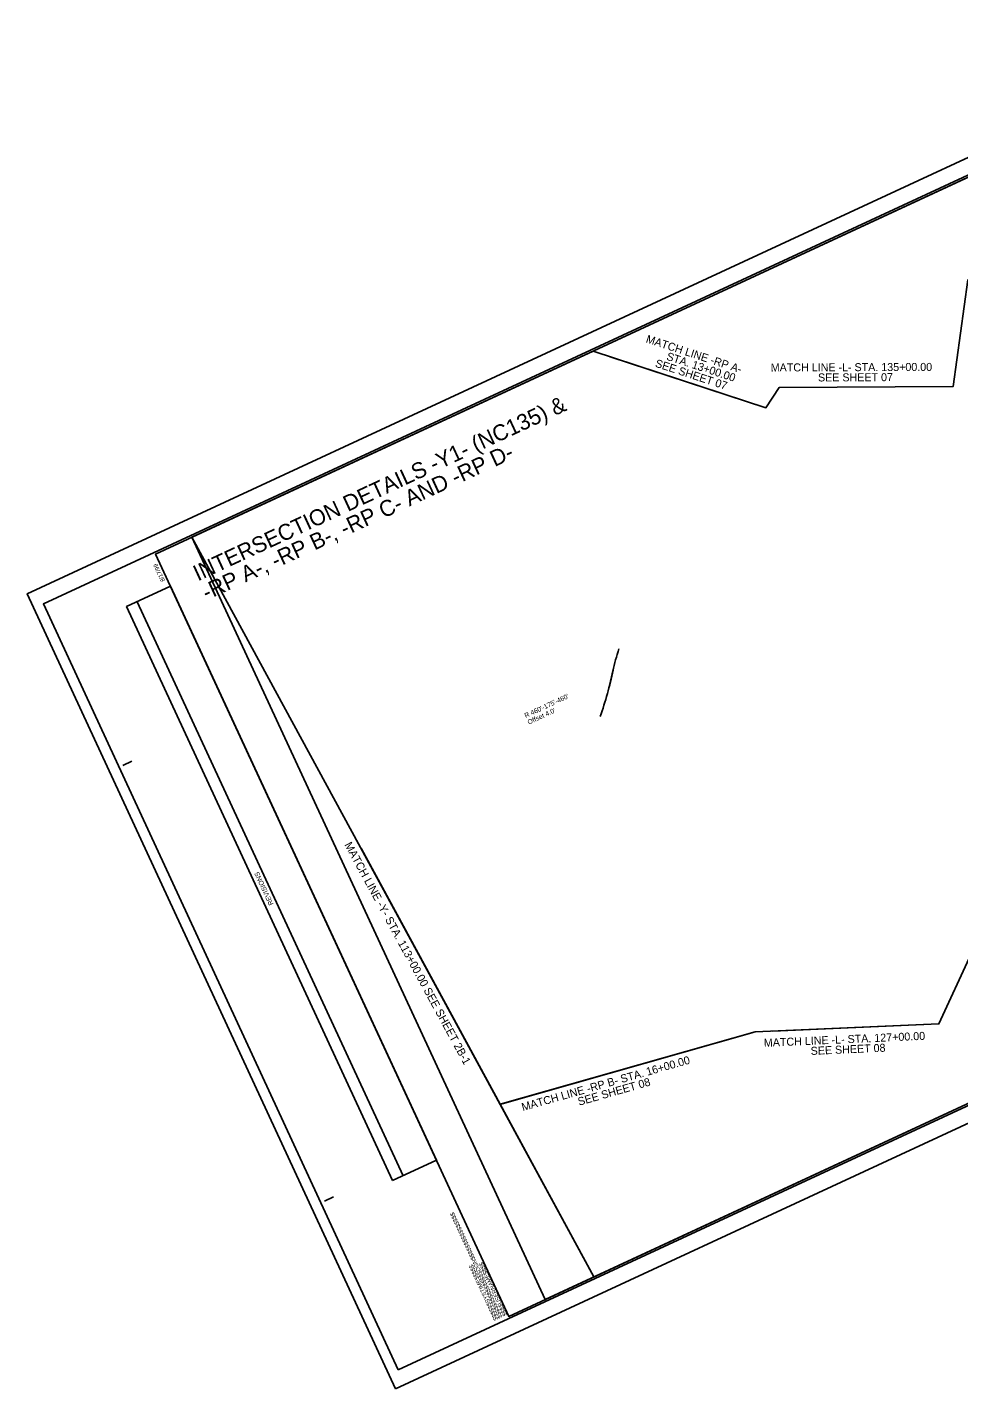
# Model space of a CAD drawing. Extents: x 1722892 to 1724880, y 971019 to 972720.
# Drawn here: x 1722892 to 1724057, y 971019 to 972720 of the extents above; entities that cross this region are included whole.
import ezdxf

# ---------------------------------------------------------------- set-up
doc = ezdxf.new("R2010")
doc.units = 0
for name, color, linetype in [('Matchline', 7, 'Continuous'), ('Matchline Text', 7, 'Continuous'), ('Prop Dimension', 7, 'Continuous'), ('Prop EOT', 7, 'Continuous'), ('Sheet Block Revision CELL', 7, 'Continuous'), ('Sheet Clip Boundary CELL', 7, 'Continuous'), ('Sheet Layout Plan Border', 7, 'Continuous'), ('Sheet Plan CELL', 7, 'Continuous'), ('Sheet Plot Border Inside CELL', 7, 'Continuous'), ('Sheet Plot Border Outside CELL', 7, 'Continuous')]:
    doc.layers.add(name, color=color, linetype=linetype)

msp = doc.modelspace()

# ---------------------------------------------------------------- linework, layer by layer
at = {"layer": 'Matchline'}
for p, q in [((1723620.9, 972308.5), (1723815.7, 972244.7)), ((1723832.3, 972270.2), (1724049.7, 972271.1)), ((1723310, 971693.4), (1723483.3, 971374.5)), ((1723797.9, 971463.5), (1723485.8, 971374.8)), ((1723824.5, 971465.6), (1724031.9, 971474.7))]:
    msp.add_line(p, q, dxfattribs=at)
at = {"layer": 'Prop Dimension'}
msp.add_line((1723620.3, 971897.8), (1723624.9, 971917.6), dxfattribs=at)
at = {"layer": 'Prop EOT'}
for centre, radius, start, end in [((1723880.9, 971861.9), 262, 161.8681, 168.1523), ((1723174.6, 972011.8), 460, 340.5756, 348.0663)]:
    msp.add_arc(centre, radius, start, end, dxfattribs=at)
at = {"layer": 'Sheet Block Revision CELL'}
msp.add_line((1723362.2, 971285), (1723029.7, 972002.4), dxfattribs=at)
msp.add_lwpolyline([(1723349, 971278.9), (1723016.5, 971996.2), (1723071.4, 972021.7), (1723403.9, 971304.4)], close=True, dxfattribs=at)
at = {"layer": 'Sheet Clip Boundary CELL'}
msp.add_lwpolyline([(1723539.6, 971130.3), (1724809.9, 971719), (1724457.3, 972479.8), (1724285.6, 972400.2), (1724196.6, 972592.1), (1723098.1, 972083)], close=True, dxfattribs=at)
at = {"layer": 'Sheet Layout Plan Border'}
for points in [[(1724374.3, 972628.7), (1724393.2, 972460.3), (1724068.1, 972404.7), (1724049.7, 972271.1), (1723832.3, 972270.2), (1723815.7, 972244.7), (1723599.7, 972315.4), (1723098.1, 972083), (1723600.7, 971158.6), (1723483.3, 971374.5), (1723802.1, 971464.7), (1724031.9, 971474.7), (1724072.2, 971562.2), (1724326.3, 971494.9), (1724493, 971572.1)], [(1724391.6, 972460.1), (1724068.1, 972404.7), (1724049.7, 972271.1), (1723832.3, 972270.2), (1723815.7, 972244.7), (1723599.7, 972315.4), (1723098.1, 972083), (1723600.7, 971158.6), (1723483.3, 971374.5), (1723802.1, 971464.7), (1724031.9, 971474.7), (1724072.2, 971562.2), (1724326.3, 971494.9), (1724488.2, 971569.9)]]:
    msp.add_lwpolyline(points, close=True, dxfattribs=at)
at = {"layer": 'Sheet Plan CELL'}
for p, q in [((1723052.8, 972061.9), (1723052.8, 972061.9)), ((1723011.6, 971797.6), (1723022.9, 971802.9)), ((1723263.9, 971253.2), (1723275.3, 971258.5)), ((1723494.3, 971109.3), (1723494.3, 971109.3))]:
    msp.add_line(p, q, dxfattribs=at)
msp.add_lwpolyline([(1724413.7, 972692.7), (1723052.8, 972061.9), (1723494.3, 971109.3), (1724855.2, 971740)], close=True, dxfattribs=at)
at = {"layer": 'Sheet Plot Border Inside CELL'}
msp.add_lwpolyline([(1723356.1, 971042.5), (1724867.6, 971743), (1724424, 972700.2), (1722912.5, 971999.7)], close=True, dxfattribs=at)
at = {"layer": 'Sheet Plot Border Outside CELL'}
msp.add_lwpolyline([(1723352.7, 971018.8), (1724880.1, 971726.7), (1724419.7, 972720.2), (1722892.3, 972012.3)], close=True, dxfattribs=at)

# ---------------------------------------------------------------- texts
at = {"layer": 'Matchline Text'}
for s, rotation, p in [('MATCH LINE -RP A- ', 341.8681, (1723664.9, 972326.6)), ('STA. 13+00.00', 341.8681, (1723690.5, 972304.9)), ('SEE SHEET 07', 341.8681, (1723676.4, 972296.2)), ('MATCH LINE -L- STA. 135+00.00', 0.2285, (1723821.7, 972290)), ('SEE SHEET 07', 0.2285, (1723880.8, 972277.6)), ('MATCH LINE -Y- STA. 113+00.00 SEE SHEET 2B-1', 298.535, (1723288.5, 971698.7)), ('MATCH LINE -L- STA. 127+00.00', 2.5198, (1723813.3, 971446.1)), ('SEE SHEET 08', 2.5198, (1723871.8, 971436)), ('MATCH LINE -RP B- STA. 16+00.00', 15.8657, (1723511.8, 971365.7)), ('SEE SHEET 08', 15.8657, (1723582.1, 971372.5))]:
    msp.add_text(s, height=10, rotation=rotation, dxfattribs=at).set_placement(p)
at = {"layer": 'Prop Dimension'}
for s, height, p in [('INTERSECTION DETAILS -Y1- (NC135) &', 20, (1723105.6, 972027.6)), ('-RP A-, -RP B-, -RP C- AND -RP D-', 20, (1723116.6, 972003.8)), ("R 460'-175'-460'", 6, (1723515.5, 971856.9)), ("Offset 4.0'", 6, (1723519.3, 971848.7))]:
    msp.add_text(s, height=height, rotation=24.8656, dxfattribs=at).set_placement(p)
at = {"layer": 'Sheet Block Revision CELL'}
msp.add_text('REVISIONS', height=6, rotation=114.8656, dxfattribs=at).set_placement((1723200.3, 971624.6))
at = {"layer": 'Sheet Plan CELL'}
for s, p in [('8/17/99', (1723064.6, 972028.6)), ('$$$$$$$$$$$$$$$$DGN$$$$$$$$$$$$$$$$', (1723486.4, 971108.2)), ('$$$$$$SYSTIME$$$$$', (1723480.9, 971105.6)), ('$$$$USERNAME$$$$', (1723492.3, 971111))]:
    msp.add_text(s, height=5.25, rotation=114.8656, dxfattribs=at).set_placement(p)

doc.saveas('drawing.dxf')
